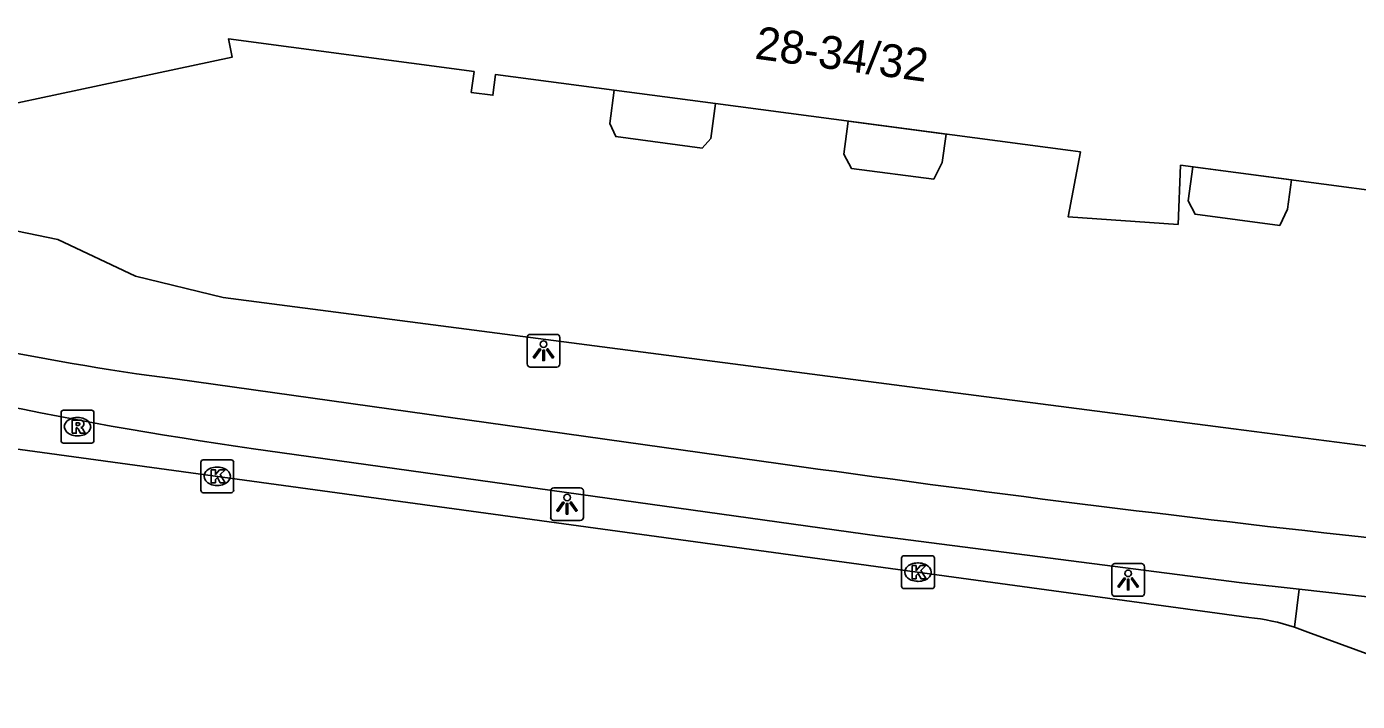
# Model space of a CAD drawing. Extents: x 160676 to 161153, y 383244 to 383713.
# Drawn here: x 160732.71 to 160773.22, y 383283.16 to 383303.71 of the extents above; entities that cross this region are included whole.
import ezdxf

# ---------------------------------------------------------------- set-up
doc = ezdxf.new("R2010")
doc.units = 0
for name, color, linetype in [('IMGEO_Berm_open', 7, 'Continuous'), ('IMGEO_Fietspad_gesloten', 7, 'Continuous'), ('IMGEO_Kolk', 7, 'Continuous'), ('IMGEO_Lichtpunt', 7, 'Continuous'), ('IMGEO_Pand', 7, 'Continuous'), ('IMGEO_Pand_nummerreeks', 7, 'Continuous'), ('IMGEO_Pand_overbouw', 7, 'Continuous'), ('IMGEO_Rijbaan_lokaal_gesloten', 7, 'Continuous'), ('IMGEO_Rioolput', 7, 'Continuous'), ('IMGEO_Voetpad_open', 7, 'Continuous')]:
    doc.layers.add(name, color=color, linetype=linetype)

msp = doc.modelspace()

# ---------------------------------------------------------------- linework, layer by layer
at = {"layer": 'IMGEO_Berm_open'}
msp.add_lwpolyline([(160771.45, 383286.574), (160771.308, 383285.419)], dxfattribs=at)
at = {"layer": 'IMGEO_Fietspad_gesloten'}
for points in [[(160737.228, 383292.98), (160755.662, 383290.395)], [(160739.615, 383290.854), (160758.605, 383288.201), (160769.706, 383286.77), (160771.45, 383286.574)], [(160771.45, 383286.574), (160777.852, 383285.853)]]:
    msp.add_lwpolyline(points, dxfattribs=at)
for centre, radius, start, end in [((160746.363, 383364.222), 71.826, 252.58268, 262.69355), ((160757.689, 383417.561), 127.99, 254.03333, 261.88177), ((160838.878, 383879.339), 594.794, 261.957551, 263.729038)]:
    msp.add_arc(centre, radius, start, end, dxfattribs=at)
at = {"layer": 'IMGEO_Kolk'}
for p, q in [((160738.011, 383289.59), (160738.011, 383290.442)), ((160738.086, 383290.516), (160738.938, 383290.516)), ((160738.499, 383290.296), (160738.524, 383290.296)), ((160739.012, 383290.442), (160739.012, 383289.59)), ((160738.938, 383289.516), (160738.086, 383289.516)), ((160738.522, 383289.736), (160738.497, 383289.736)), ((160759.344, 383286.669), (160759.344, 383287.521)), ((160759.419, 383287.595), (160760.271, 383287.595)), ((160760.345, 383287.521), (160760.345, 383286.669)), ((160759.832, 383287.375), (160759.857, 383287.375)), ((160760.271, 383286.595), (160759.419, 383286.595)), ((160759.855, 383286.815), (160759.83, 383286.815))]:
    msp.add_line(p, q, dxfattribs=at)
for points in [[(160738.011, 383289.59), (160738.011, 383290.442)], [(160738.086, 383290.516), (160738.938, 383290.516)], [(160739.012, 383290.442), (160739.012, 383289.59)], [(160738.332, 383290.216), (160738.455, 383290.216), (160738.455, 383290.065), (160738.585, 383290.216), (160738.749, 383290.216), (160738.603, 383290.065), (160738.756, 383289.816), (160738.604, 383289.816), (160738.519, 383289.98), (160738.455, 383289.913), (160738.455, 383289.816), (160738.332, 383289.816), (160738.332, 383290.216)], [(160738.938, 383289.516), (160738.086, 383289.516)], [(160759.344, 383286.669), (160759.344, 383287.521)], [(160759.419, 383287.595), (160760.271, 383287.595)], [(160760.345, 383287.521), (160760.345, 383286.669)], [(160759.665, 383287.295), (160759.788, 383287.295), (160759.788, 383287.144), (160759.918, 383287.295), (160760.082, 383287.295), (160759.936, 383287.144), (160760.089, 383286.895), (160759.937, 383286.895), (160759.852, 383287.059), (160759.788, 383286.992), (160759.788, 383286.895), (160759.665, 383286.895), (160759.665, 383287.295)], [(160760.271, 383286.595), (160759.419, 383286.595)]]:
    msp.add_lwpolyline(points, dxfattribs=at)
for centre, start, end in [((160738.088, 383290.44), 91.552, 178.448), ((160738.088, 383290.44), 91.552, 178.448), ((160738.936, 383290.44), 1.552, 88.448), ((160738.936, 383290.44), 1.552, 88.448), ((160738.088, 383289.592), 181.552, 268.448), ((160738.088, 383289.592), 181.552, 268.448), ((160738.936, 383289.592), 271.552, 358.448), ((160738.936, 383289.592), 271.552, 358.448), ((160759.421, 383287.519), 91.552, 178.448), ((160759.421, 383287.519), 91.552, 178.448), ((160760.269, 383287.519), 1.552, 88.448), ((160760.269, 383287.519), 1.552, 88.448), ((160759.421, 383286.671), 181.552, 268.448), ((160759.421, 383286.671), 181.552, 268.448), ((160760.269, 383286.671), 271.552, 358.448), ((160760.269, 383286.671), 271.552, 358.448)]:
    msp.add_arc(centre, 0.0765, start, end, dxfattribs=at)
for centre, major_axis, ratio, start_param, end_param in [((160738.498, 383290.016), (-0.387, 0.002), 0.722429, 4.712389, 7.853982), ((160738.523, 383290.016), (-0.39, 0.002), 0.717154, 1.570796, 4.712389), ((160759.831, 383287.095), (-0.387, 0.002), 0.722429, 4.712389, 7.853982), ((160759.856, 383287.095), (-0.39, 0.002), 0.717154, 1.570796, 4.712389)]:
    msp.add_ellipse(centre, major_axis=major_axis, ratio=ratio, start_param=start_param, end_param=end_param, dxfattribs=at)
at = {"layer": 'IMGEO_Lichtpunt'}
for p, q in [((160748.849, 383294.339), (160748.041, 383294.339)), ((160748.849, 383294.339), (160748.041, 383294.339)), ((160747.947, 383294.244), (160747.947, 383293.437)), ((160747.947, 383294.244), (160747.947, 383293.437)), ((160748.943, 383293.437), (160748.943, 383294.244)), ((160748.943, 383293.437), (160748.943, 383294.244)), ((160748.041, 383293.343), (160748.849, 383293.343)), ((160748.041, 383293.343), (160748.849, 383293.343)), ((160748.663, 383289.571), (160748.663, 383288.764)), ((160748.663, 383289.571), (160748.663, 383288.764)), ((160749.565, 383289.666), (160748.757, 383289.666)), ((160749.565, 383289.666), (160748.757, 383289.666)), ((160749.659, 383288.764), (160749.659, 383289.571)), ((160749.659, 383288.764), (160749.659, 383289.571)), ((160748.757, 383288.67), (160749.565, 383288.67)), ((160748.757, 383288.67), (160749.565, 383288.67)), ((160765.745, 383287.261), (160765.745, 383286.454)), ((160765.745, 383287.261), (160765.745, 383286.454)), ((160766.647, 383287.356), (160765.839, 383287.356)), ((160766.647, 383287.356), (160765.839, 383287.356)), ((160766.741, 383286.454), (160766.741, 383287.261)), ((160766.741, 383286.454), (160766.741, 383287.261)), ((160765.839, 383286.36), (160766.647, 383286.36)), ((160765.839, 383286.36), (160766.647, 383286.36))]:
    msp.add_line(p, q, dxfattribs=at)
for points in [[(160748.321, 383293.908), (160748.36, 383293.88), (160748.172, 383293.618), (160748.134, 383293.645), (160748.321, 383293.908)], [(160748.533, 383293.88), (160748.571, 383293.907), (160748.758, 383293.645), (160748.719, 383293.617), (160748.533, 383293.88)], [(160748.423, 383293.86), (160748.47, 383293.86), (160748.47, 383293.538), (160748.423, 383293.538), (160748.423, 383293.86)], [(160749.037, 383289.235), (160749.076, 383289.207), (160748.888, 383288.945), (160748.85, 383288.972), (160749.037, 383289.235)], [(160749.139, 383289.187), (160749.186, 383289.187), (160749.186, 383288.865), (160749.139, 383288.865), (160749.139, 383289.187)], [(160749.249, 383289.207), (160749.287, 383289.234), (160749.474, 383288.972), (160749.435, 383288.944), (160749.249, 383289.207)], [(160766.119, 383286.925), (160766.158, 383286.897), (160765.97, 383286.635), (160765.932, 383286.662), (160766.119, 383286.925)], [(160766.221, 383286.877), (160766.268, 383286.877), (160766.268, 383286.555), (160766.221, 383286.555), (160766.221, 383286.877)], [(160766.331, 383286.897), (160766.369, 383286.924), (160766.556, 383286.662), (160766.517, 383286.634), (160766.331, 383286.897)]]:
    msp.add_lwpolyline(points, dxfattribs=at)
for centre in [(160748.446, 383294.042), (160749.162, 383289.369), (160766.244, 383287.059)]:
    msp.add_circle(centre, 0.0994, dxfattribs=at)
for centre, start, end in [((160748.041, 383294.244), 90, 180), ((160748.041, 383294.244), 90, 180), ((160748.849, 383294.244), 0, 90), ((160748.849, 383294.244), 0, 90), ((160748.041, 383293.437), 180, 270), ((160748.041, 383293.437), 180, 270), ((160748.849, 383293.437), 270, 0), ((160748.849, 383293.437), 270, 360), ((160748.757, 383289.571), 90, 180), ((160748.757, 383289.571), 90, 180), ((160749.565, 383289.571), 0, 90), ((160749.565, 383289.571), 0, 90), ((160748.757, 383288.764), 180, 270), ((160748.757, 383288.764), 180, 270), ((160749.565, 383288.764), 270, 0), ((160749.565, 383288.764), 270, 360), ((160765.839, 383287.261), 90, 180), ((160765.839, 383287.261), 90, 180), ((160766.647, 383287.261), 0, 90), ((160766.647, 383287.261), 0, 90), ((160765.839, 383286.454), 180, 270), ((160765.839, 383286.454), 180, 270), ((160766.647, 383286.454), 270, 0), ((160766.647, 383286.454), 270, 360)]:
    msp.add_arc(centre, 0.0946, start, end, dxfattribs=at)
at = {"layer": 'IMGEO_Pand'}
msp.add_lwpolyline([(160726.669, 383300.167), (160738.971, 383302.787), (160738.853, 383303.338), (160746.332, 383302.345), (160746.246, 383301.706), (160746.904, 383301.62), (160746.986, 383302.258), (160750.598, 383301.779), (160753.68, 383301.37), (160764.483, 383299.936), (160764.788, 383299.895), (160764.421, 383297.916), (160764.421, 383297.914), (160767.765, 383297.687), (160767.84, 383299.49), (160774.882, 383298.555)], dxfattribs=at)
at = {"layer": 'IMGEO_Pand_overbouw'}
for points in [[(160753.68, 383301.37), (160750.598, 383301.779), (160750.464, 383300.766), (160750.644, 383300.362), (160753.27, 383300.013), (160753.538, 383300.306)], [(160757.718, 383300.834), (160757.584, 383299.826), (160757.819, 383299.393), (160760.323, 383299.061), (160760.584, 383299.575), (160760.699, 383300.438)], [(160768.212, 383299.441), (160768.074, 383298.406), (160768.28, 383297.996), (160770.858, 383297.654), (160771.098, 383298.152), (160771.216, 383299.042)]]:
    msp.add_lwpolyline(points, close=True, dxfattribs=at)
at = {"layer": 'IMGEO_Rijbaan_lokaal_gesloten'}
for points in [[(160769.912, 383285.718), (160720.857, 383292.423)], [(160777.552, 383283.158), (160777.187, 383283.264), (160771.71, 383285.271), (160771.308, 383285.419)]]:
    msp.add_lwpolyline(points, dxfattribs=at)
msp.add_arc((160769.234, 383279.143), 6.61, 71.7112, 84.1105, dxfattribs=at)
at = {"layer": 'IMGEO_Rioolput'}
for p, q in [((160733.757, 383291.1), (160733.757, 383291.952)), ((160733.832, 383292.026), (160734.684, 383292.026)), ((160734.758, 383291.952), (160734.758, 383291.1)), ((160734.245, 383291.806), (160734.27, 383291.806)), ((160734.268, 383291.246), (160734.243, 383291.246)), ((160734.684, 383291.026), (160733.832, 383291.026))]:
    msp.add_line(p, q, dxfattribs=at)
for points in [[(160733.757, 383291.1), (160733.757, 383291.952)], [(160733.832, 383292.026), (160734.684, 383292.026)], [(160734.758, 383291.952), (160734.758, 383291.1)], [(160734.346, 383291.724), (160734.094, 383291.726), (160734.094, 383291.326)], [(160734.094, 383291.326), (160734.218, 383291.326), (160734.218, 383291.488), (160734.229, 383291.488)], [(160734.272, 383291.645), (160734.218, 383291.645), (160734.218, 383291.564)], [(160734.218, 383291.564), (160734.27, 383291.564)], [(160734.276, 383291.459), (160734.347, 383291.326), (160734.487, 383291.326), (160734.422, 383291.452)], [(160734.684, 383291.026), (160733.832, 383291.026)]]:
    msp.add_lwpolyline(points, dxfattribs=at)
for centre, radius, start, end in [((160733.834, 383291.95), 0.0765, 91.552, 178.448), ((160733.834, 383291.95), 0.0765, 91.552, 178.448), ((160734.682, 383291.95), 0.0765, 1.552, 88.448), ((160734.682, 383291.95), 0.0765, 1.552, 88.448), ((160734.228, 383291.435), 0.0533, 26.0293, 88.6989), ((160734.254, 383291.753), 0.19, 274.7715, 282.9687), ((160734.278, 383291.549), 0.0964, 77.0061, 93.1865), ((160734.292, 383291.606), 0.0378, 276.6634, 79.6772), ((160734.345, 383291.614), 0.109, 350.3612, 89.416), ((160734.343, 383291.614), 0.112, 277.5842, 350.9817), ((160734.327, 383291.399), 0.108, 29.5134, 73.7905), ((160733.834, 383291.102), 0.0765, 181.552, 268.448), ((160733.834, 383291.102), 0.0765, 181.552, 268.448), ((160734.682, 383291.102), 0.0765, 271.552, 358.448), ((160734.682, 383291.102), 0.0765, 271.552, 358.448)]:
    msp.add_arc(centre, radius, start, end, dxfattribs=at)
for centre, major_axis, ratio, start_param, end_param in [((160734.244, 383291.526), (-0.387, 0.002), 0.722429, 4.712389, 7.853982), ((160734.269, 383291.526), (-0.39, 0.002), 0.717154, 1.570796, 4.712389)]:
    msp.add_ellipse(centre, major_axis=major_axis, ratio=ratio, start_param=start_param, end_param=end_param, dxfattribs=at)
at = {"layer": 'IMGEO_Voetpad_open'}
msp.add_lwpolyline([(160773.221, 383290.971), (160769.45, 383291.461), (160761.067, 383292.551), (160738.693, 383295.459), (160736.023, 383296.113), (160733.661, 383297.23), (160720.82, 383299.881), (160720.042, 383300.069)], dxfattribs=at)
msp.add_arc((160774.582, 383301.91), 11.023, 262.9096, 313.4171, dxfattribs=at)

# ---------------------------------------------------------------- texts
at = {"layer": 'IMGEO_Pand_nummerreeks'}
msp.add_text('28-34/32', height=1, rotation=352.2422, dxfattribs=at).set_placement((160754.85, 383302.741))

doc.saveas('drawing.dxf')
